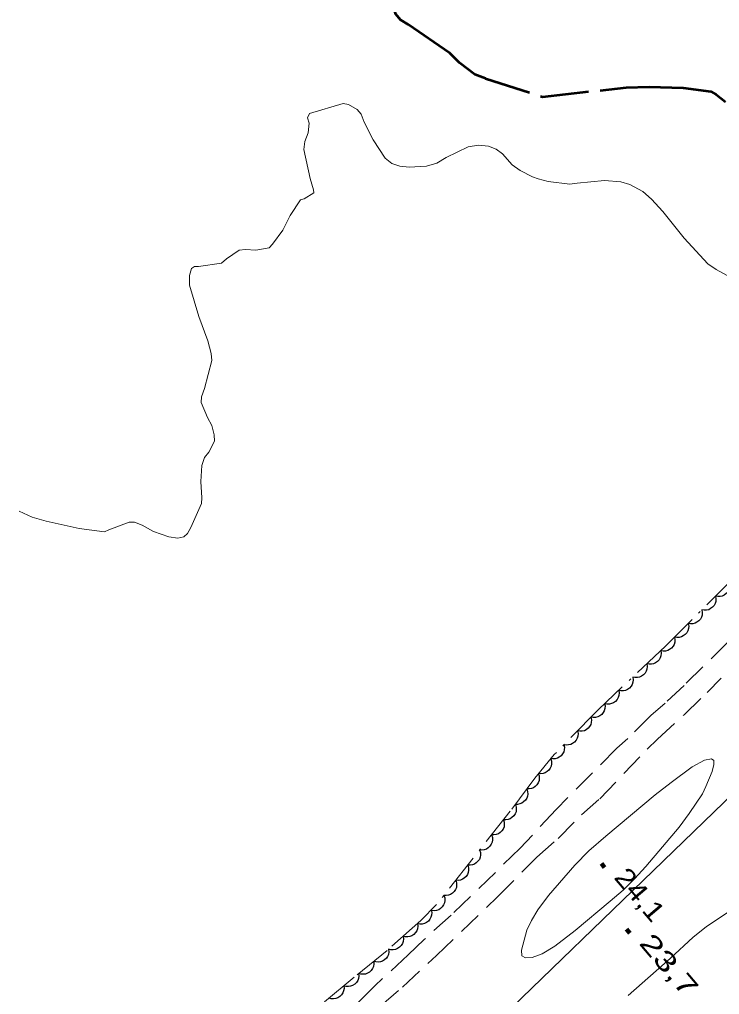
# Model space of a CAD drawing. Extents: x 386081 to 389416, y 5130568 to 5134082.
# Drawn here: x 387638.7 to 387747.5, y 5131418.1 to 5131569.7 of the extents above; entities that cross this region are included whole.
import ezdxf

# ---------------------------------------------------------------- set-up
doc = ezdxf.new("R2010")
doc.units = 0
doc.header["$LTSCALE"] = 1.2
for name, pattern in [('DOT_DASHED', [7.7, 5, -1.2, 0.3, -1.2]), ('LONG_DASHED', [7.5, 6, -1.5]), ('MEDIUM_DASHED', [4.5, 3, -1.5])]:
    doc.linetypes.add(name, pattern=pattern)
for name, color, linetype, lineweight in [('1', 7, 'Continuous', 53), ('19', 7, 'Continuous', 13), ('2', 7, 'Continuous', 13), ('3', 7, 'Continuous', 140), ('36', 7, 'Continuous', 13), ('44', 7, 'Continuous', 25)]:
    doc.layers.add(name, color=color, linetype=linetype, lineweight=lineweight)

msp = doc.modelspace()

# ---------------------------------------------------------------- linework, layer by layer
at = {"layer": '1'}
msp.add_lwpolyline([(387711.11, 5131560.55), (387709.47, 5131561.18), (387707.05, 5131563.01), (387705.56, 5131564.5), (387699.1, 5131568.97), (387697.92, 5131569.69), (387697.17, 5131570.57), (387695.67, 5131574.86), (387695.47, 5131575.7), (387697.33, 5131579.84), (387697.92, 5131580.91), (387698.4, 5131584.57), (387698.43, 5131586.46)], dxfattribs=at)
at = {"layer": '1', "linetype": 'LONG_DASHED'}
msp.add_lwpolyline([(387711.11, 5131560.55), (387719.99, 5131557.72), (387732.98, 5131559.16), (387736.59, 5131559.25), (387741.87, 5131559.09), (387746.16, 5131558.55), (387746.99, 5131558.09), (387748.45, 5131556.95)], dxfattribs=at)
at = {"layer": '19', "linetype": 'MEDIUM_DASHED'}
for points in [[(387767.18, 5131501.26), (387773.01, 5131498.47), (387778.91, 5131496.16), (387773.75, 5131492.65), (387765.37, 5131487.52), (387758.94, 5131482.24), (387753.31, 5131476.77), (387748.74, 5131472.81), (387742, 5131466.14), (387739.04, 5131463.38), (387736.82, 5131461.46), (387733.23, 5131457.86), (387731.56, 5131456.36), (387722.08, 5131446.83), (387716.52, 5131440.82), (387705.78, 5131430.39), (387701.56, 5131426.6), (387699.09, 5131424.2), (387693.91, 5131419.41), (387689.35, 5131414.74)], [(387694.88, 5131416.33), (387698.21, 5131419.2), (387703.49, 5131424.13), (387712.98, 5131433.23), (387719.09, 5131439.41), (387722.39, 5131442.33), (387726.03, 5131445.99), (387728.87, 5131448.51), (387736.26, 5131456.24), (387737.86, 5131457.8), (387742, 5131461.58), (387745.59, 5131465.06), (387747.75, 5131467.29)]]:
    msp.add_lwpolyline(points, dxfattribs=at)
at = {"layer": '2'}
for points in [[(387638.61, 5131493.23), (387640.62, 5131492.3), (387642.8, 5131491.68), (387647.94, 5131490.53), (387651.89, 5131490.04), (387652.54, 5131490.36), (387655.7, 5131491.54), (387656.52, 5131491.53), (387657.71, 5131491.09), (387659.51, 5131490.11), (387661.86, 5131489.24), (387663.26, 5131489.04), (387664.23, 5131489.28), (387664.79, 5131489.78), (387665.31, 5131490.71), (387666.97, 5131494.43), (387667.02, 5131495.32), (387666.86, 5131497.87), (387667.01, 5131500.37), (387667.42, 5131501.59), (387668.08, 5131502.43), (387668.97, 5131504.13), (387668.95, 5131505.13), (387668.58, 5131506.59), (387667.89, 5131507.8), (387666.93, 5131510.15), (387666.94, 5131511.05), (387667.41, 5131512.34), (387668.56, 5131516.71), (387668.48, 5131517.8), (387667.94, 5131519.76), (387666.53, 5131523.54), (387665.1, 5131528.41), (387665.07, 5131529.9), (387665.39, 5131531.01), (387665.85, 5131531.29), (387666.49, 5131531.3), (387670.09, 5131531.84), (387670.83, 5131532.51), (387672.82, 5131533.84), (387673.8, 5131533.97), (387675.38, 5131533.86), (387677.46, 5131534.23), (387678.01, 5131534.8), (387679.58, 5131536.96), (387680.76, 5131539.26), (387682.36, 5131541.69), (387682.9, 5131541.84), (387684.42, 5131542.75), (387684.39, 5131543.22), (387683.87, 5131545.01), (387682.89, 5131549.51), (387683.02, 5131550.78), (387683.52, 5131552.09), (387683.69, 5131553.59), (387683.46, 5131554.42), (387683.77, 5131555.12), (387689, 5131556.68), (387689.8, 5131556.51), (387691.17, 5131555.76), (387691.77, 5131554.99), (387692.24, 5131553.75), (387693.63, 5131551.01), (387695.53, 5131548.18), (387696.56, 5131547.32), (387697.82, 5131546.9), (387699.24, 5131546.79), (387701.94, 5131546.9), (387703.57, 5131547.38), (387704.99, 5131548.25), (387708.44, 5131549.92), (387710.02, 5131550.17), (387711.56, 5131550.05), (387712.78, 5131549.58), (387713.74, 5131548.83), (387715.28, 5131547.13), (387716.52, 5131546.26), (387718.45, 5131545.26)], [(387733.29, 5131417.89), (387739.83, 5131423.64), (387743.41, 5131426.99), (387745.44, 5131428.6), (387750.92, 5131432.24), (387753.07, 5131433.49), (387757.74, 5131435.98), (387760.94, 5131437.88), (387765, 5131440.5), (387766.54, 5131441.64), (387767.12, 5131442.53), (387768.11, 5131442.82), (387769.89, 5131443.69), (387771.65, 5131444.96), (387772.45, 5131445.94), (387773.47, 5131447.76), (387775.52, 5131450.78), (387781.23, 5131458.62), (387782.58, 5131459.76), (387784.66, 5131461.94), (387785.78, 5131463.55), (387787.12, 5131466), (387791.94, 5131474.18), (387792.11, 5131474.25)]]:
    msp.add_lwpolyline(points, dxfattribs=at)
at = {"layer": '2', "linetype": 'LONG_DASHED'}
msp.add_lwpolyline([(387718.45, 5131545.26), (387719.29, 5131544.94), (387720.85, 5131544.55), (387724.25, 5131544.11), (387725.39, 5131544.3), (387729.61, 5131544.69), (387732.18, 5131544.5), (387733.58, 5131544.05), (387735.57, 5131542.99), (387736.94, 5131541.79), (387738.67, 5131539.88), (387742.02, 5131535.7), (387745.7, 5131531.73), (387746.99, 5131530.84), (387749.72, 5131529.33)], dxfattribs=at)
at = {"layer": '2'}
msp.add_lwpolyline([(387742.79, 5131446.19), (387744.84, 5131449.27), (387745.4, 5131450.41), (387746.35, 5131452.77), (387746.6, 5131453.86), (387746.61, 5131454.47), (387746.25, 5131454.72), (387745.15, 5131454.49), (387743.24, 5131453.48), (387739.98, 5131451.03), (387737.51, 5131449.12), (387729.81, 5131442.71), (387727.16, 5131440.38), (387725, 5131438.16), (387720.92, 5131433.48), (387719.24, 5131431.25), (387718.25, 5131429.56), (387717.56, 5131428.05), (387716.73, 5131424.97), (387716.78, 5131424.06), (387717.32, 5131423.75), (387718.36, 5131423.79), (387719.95, 5131424.38), (387721.92, 5131425.57), (387725.06, 5131428.02), (387730.48, 5131432.56), (387732.51, 5131434.3), (387734.3, 5131436.04), (387736.03, 5131437.96), (387741.23, 5131444.09)], close=True, dxfattribs=at)
at = {"layer": '3'}
for p, q in [((387729.13, 5131438.43), (387729.64, 5131437.82)), ((387733.03, 5131428.2), (387733.54, 5131427.59))]:
    msp.add_line(p, q, dxfattribs=at)
at = {"layer": '36', "lineweight": 25}
msp.add_lwpolyline([(387556.24, 5131263.48), (387630.23, 5131333.84), (387913.32, 5131607.74), (388190.17, 5131875.78), (388476.11, 5132152.28), (388734, 5132401.95), (388752.8, 5132419.88)], dxfattribs=at)
at = {"layer": '44', "linetype": 'DOT_DASHED', "lineweight": 13}
msp.add_lwpolyline([(387749.77, 5131482.91), (387739.1, 5131472.26), (387728.61, 5131462.32), (387721.81, 5131455.38), (387718.77, 5131451.71), (387714.93, 5131446.55), (387703.52, 5131432.04), (387701.04, 5131429.55), (387695.83, 5131424.91), (387690.7, 5131420.76), (387673.46, 5131406.37)], dxfattribs=at)
at = {"layer": '44'}
for points in [[(387749, 5131482.14), (387749.08, 5131481.73), (387749.04, 5131481.33), (387748.96, 5131481.01), (387748.78, 5131480.7), (387748.54, 5131480.42), (387748.23, 5131480.2), (387747.94, 5131480.04), (387747.6, 5131479.97), (387747.23, 5131479.95), (387746.88, 5131480.02)], [(387746.88, 5131480.02), (387746.95, 5131479.61), (387746.91, 5131479.21), (387746.83, 5131478.89), (387746.66, 5131478.58), (387746.42, 5131478.3), (387746.11, 5131478.08), (387745.82, 5131477.92), (387745.48, 5131477.85), (387745.11, 5131477.83), (387744.75, 5131477.9)], [(387744.75, 5131477.9), (387744.83, 5131477.49), (387744.79, 5131477.09), (387744.71, 5131476.77), (387744.53, 5131476.46), (387744.3, 5131476.18), (387743.98, 5131475.96), (387743.7, 5131475.8), (387743.35, 5131475.73), (387742.98, 5131475.71), (387742.63, 5131475.78)], [(387742.63, 5131475.78), (387742.71, 5131475.37), (387742.67, 5131474.97), (387742.59, 5131474.65), (387742.41, 5131474.34), (387742.17, 5131474.06), (387741.86, 5131473.84), (387741.58, 5131473.68), (387741.23, 5131473.61), (387740.86, 5131473.6), (387740.51, 5131473.66)], [(387740.51, 5131473.66), (387740.58, 5131473.25), (387740.54, 5131472.85), (387740.46, 5131472.53), (387740.29, 5131472.22), (387740.05, 5131471.94), (387739.74, 5131471.72), (387739.45, 5131471.56), (387739.11, 5131471.49), (387738.74, 5131471.48), (387738.38, 5131471.54)], [(387738.36, 5131471.56), (387738.43, 5131471.15), (387738.38, 5131470.75), (387738.29, 5131470.43), (387738.11, 5131470.13), (387737.86, 5131469.85), (387737.54, 5131469.64), (387737.26, 5131469.49), (387736.91, 5131469.43), (387736.54, 5131469.42), (387736.19, 5131469.5)], [(387736.19, 5131469.5), (387736.25, 5131469.09), (387736.2, 5131468.68), (387736.12, 5131468.37), (387735.93, 5131468.07), (387735.69, 5131467.79), (387735.37, 5131467.58), (387735.08, 5131467.42), (387734.73, 5131467.36), (387734.36, 5131467.36), (387734.01, 5131467.44)], [(387734.01, 5131467.44), (387734.08, 5131467.02), (387734.02, 5131466.62), (387733.94, 5131466.3), (387733.75, 5131466), (387733.51, 5131465.73), (387733.19, 5131465.51), (387732.9, 5131465.36), (387732.55, 5131465.3), (387732.18, 5131465.3), (387731.83, 5131465.37)], [(387731.83, 5131465.37), (387731.9, 5131464.96), (387731.85, 5131464.56), (387731.76, 5131464.24), (387731.57, 5131463.94), (387731.33, 5131463.66), (387731.01, 5131463.45), (387730.72, 5131463.3), (387730.38, 5131463.24), (387730.01, 5131463.23), (387729.65, 5131463.31)], [(387729.62, 5131463.35), (387729.7, 5131462.94), (387729.66, 5131462.53), (387729.59, 5131462.21), (387729.41, 5131461.91), (387729.18, 5131461.62), (387728.87, 5131461.39), (387728.59, 5131461.23), (387728.24, 5131461.16), (387727.87, 5131461.14), (387727.52, 5131461.2)], [(387727.52, 5131461.2), (387727.6, 5131460.79), (387727.56, 5131460.39), (387727.49, 5131460.07), (387727.31, 5131459.76), (387727.08, 5131459.48), (387726.77, 5131459.25), (387726.49, 5131459.09), (387726.14, 5131459.01), (387725.77, 5131459), (387725.42, 5131459.06)], [(387725.42, 5131459.06), (387725.5, 5131458.65), (387725.46, 5131458.25), (387725.39, 5131457.93), (387725.21, 5131457.62), (387724.98, 5131457.33), (387724.67, 5131457.11), (387724.39, 5131456.95), (387724.04, 5131456.87), (387723.67, 5131456.85), (387723.32, 5131456.92)], [(387723.32, 5131456.92), (387723.4, 5131456.51), (387723.36, 5131456.1), (387723.29, 5131455.78), (387723.11, 5131455.48), (387722.88, 5131455.19), (387722.57, 5131454.97), (387722.29, 5131454.8), (387721.94, 5131454.73), (387721.57, 5131454.71), (387721.22, 5131454.78)], [(387721.27, 5131454.73), (387721.39, 5131454.33), (387721.38, 5131453.92), (387721.34, 5131453.59), (387721.19, 5131453.27), (387720.98, 5131452.97), (387720.69, 5131452.72), (387720.42, 5131452.53), (387720.08, 5131452.43), (387719.71, 5131452.38), (387719.36, 5131452.42)], [(387719.32, 5131452.45), (387719.46, 5131452.05), (387719.47, 5131451.65), (387719.44, 5131451.32), (387719.31, 5131450.99), (387719.12, 5131450.68), (387718.84, 5131450.41), (387718.58, 5131450.21), (387718.25, 5131450.09), (387717.89, 5131450.03), (387717.53, 5131450.04)], [(387717.53, 5131450.04), (387717.67, 5131449.65), (387717.68, 5131449.24), (387717.65, 5131448.91), (387717.52, 5131448.58), (387717.33, 5131448.27), (387717.05, 5131448.01), (387716.79, 5131447.81), (387716.46, 5131447.69), (387716.1, 5131447.62), (387715.74, 5131447.63)], [(387715.77, 5131447.61), (387715.89, 5131447.21), (387715.9, 5131446.81), (387715.86, 5131446.48), (387715.72, 5131446.16), (387715.52, 5131445.85), (387715.23, 5131445.59), (387714.97, 5131445.4), (387714.64, 5131445.29), (387714.27, 5131445.23), (387713.91, 5131445.25)], [(387713.91, 5131445.25), (387714.04, 5131444.86), (387714.04, 5131444.45), (387714.01, 5131444.12), (387713.87, 5131443.8), (387713.66, 5131443.49), (387713.38, 5131443.23), (387713.12, 5131443.04), (387712.78, 5131442.93), (387712.42, 5131442.87), (387712.06, 5131442.9)], [(387712.06, 5131442.9), (387712.18, 5131442.5), (387712.19, 5131442.09), (387712.15, 5131441.76), (387712.01, 5131441.44), (387711.81, 5131441.13), (387711.53, 5131440.87), (387711.26, 5131440.68), (387710.93, 5131440.57), (387710.56, 5131440.51), (387710.2, 5131440.54)], [(387710.2, 5131440.54), (387710.33, 5131440.14), (387710.34, 5131439.73), (387710.3, 5131439.41), (387710.16, 5131439.08), (387709.95, 5131438.77), (387709.67, 5131438.52), (387709.41, 5131438.32), (387709.07, 5131438.21), (387708.71, 5131438.15), (387708.35, 5131438.18)], [(387708.35, 5131438.18), (387708.48, 5131437.78), (387708.48, 5131437.38), (387708.44, 5131437.05), (387708.3, 5131436.72), (387708.1, 5131436.42), (387707.82, 5131436.16), (387707.55, 5131435.97), (387707.22, 5131435.85), (387706.85, 5131435.8), (387706.49, 5131435.82)], [(387706.49, 5131435.82), (387706.62, 5131435.42), (387706.63, 5131435.02), (387706.59, 5131434.69), (387706.45, 5131434.37), (387706.25, 5131434.06), (387705.96, 5131433.8), (387705.7, 5131433.61), (387705.36, 5131433.5), (387705, 5131433.44), (387704.64, 5131433.46)], [(387704.64, 5131433.46), (387704.77, 5131433.07), (387704.77, 5131432.66), (387704.73, 5131432.33), (387704.59, 5131432.01), (387704.39, 5131431.7), (387704.11, 5131431.44), (387703.84, 5131431.25), (387703.51, 5131431.14), (387703.14, 5131431.08), (387702.78, 5131431.1)], [(387702.68, 5131431.2), (387702.76, 5131430.79), (387702.72, 5131430.38), (387702.64, 5131430.06), (387702.47, 5131429.76), (387702.23, 5131429.47), (387701.92, 5131429.25), (387701.63, 5131429.09), (387701.29, 5131429.02), (387700.92, 5131429), (387700.56, 5131429.07)], [(387700.54, 5131429.1), (387700.59, 5131428.69), (387700.53, 5131428.29), (387700.43, 5131427.97), (387700.24, 5131427.68), (387699.98, 5131427.41), (387699.66, 5131427.2), (387699.36, 5131427.06), (387699.02, 5131427.01), (387698.64, 5131427.02), (387698.3, 5131427.11)], [(387698.3, 5131427.11), (387698.35, 5131426.69), (387698.29, 5131426.29), (387698.19, 5131425.97), (387697.99, 5131425.68), (387697.74, 5131425.41), (387697.42, 5131425.21), (387697.12, 5131425.07), (387696.77, 5131425.01), (387696.4, 5131425.02), (387696.06, 5131425.11)], [(387696.06, 5131425.1), (387696.1, 5131424.68), (387696.02, 5131424.29), (387695.9, 5131423.97), (387695.7, 5131423.69), (387695.43, 5131423.43), (387695.1, 5131423.25), (387694.8, 5131423.12), (387694.45, 5131423.08), (387694.08, 5131423.11), (387693.73, 5131423.21)], [(387693.73, 5131423.21), (387693.77, 5131422.8), (387693.68, 5131422.4), (387693.57, 5131422.09), (387693.36, 5131421.8), (387693.1, 5131421.55), (387692.76, 5131421.36), (387692.46, 5131421.23), (387692.11, 5131421.2), (387691.74, 5131421.22), (387691.4, 5131421.33)], [(387691.39, 5131421.34), (387691.43, 5131420.92), (387691.35, 5131420.52), (387691.25, 5131420.21), (387691.04, 5131419.92), (387690.78, 5131419.66), (387690.45, 5131419.47), (387690.15, 5131419.34), (387689.8, 5131419.3), (387689.43, 5131419.31), (387689.09, 5131419.41)], [(387689.09, 5131419.41), (387689.13, 5131419), (387689.05, 5131418.6), (387688.94, 5131418.29), (387688.74, 5131418), (387688.48, 5131417.74), (387688.15, 5131417.55), (387687.85, 5131417.41), (387687.5, 5131417.37), (387687.13, 5131417.39), (387686.78, 5131417.49)]]:
    msp.add_lwpolyline(points, dxfattribs=at)

# ---------------------------------------------------------------- texts
at = {"layer": '3'}
for s, width, p in [('24,1   ', 1.2, (387730.96, 5131436.21)), ('23,7   ', 1.45, (387734.86, 5131425.98))]:
    msp.add_text(s, height=3, rotation=310.294, dxfattribs=dict(at, width=width)).set_placement(p)

doc.saveas('drawing.dxf')
